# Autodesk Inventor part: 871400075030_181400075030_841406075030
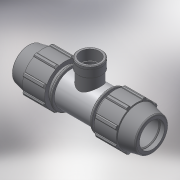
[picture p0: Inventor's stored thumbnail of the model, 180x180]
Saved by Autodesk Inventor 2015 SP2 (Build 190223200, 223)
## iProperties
Created: 2017-02
Part Number: 871400075030_181400075030_841406075030
Material: Generic
Description: PLASSON TEE WITH THREADED FEMALE OFFTAKE 75-3"-75
Document SubType Name: Modeling
Designer: KIM
Mass: 92.6774 g
Surface Area: 199.44 cm^2
Volume: 66.1981 cm^3
Density: 1 g/cm^3
Appearance: Default
Author: KIM
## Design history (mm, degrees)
derived "87140.ipt"
feature "Solid1::87140.ipt"
feature "Solid2::87140.ipt"
tag "TaggingFeature1"
body "Solid1"
other parameters: "d2" = 75, "d4" = 15.41667, "d5" = 44.4, "d7" = 132, "d11" = 6.16667, "d13" = 120 deg, "d14" = 97.5, "d15" = 12 deg, "d16" = 114.84, "d18" = 3.75, "d19" = 35 deg, "d20" = 17.5 deg, "d21" = 122.76, "d23" = 0, "d25" = 360 deg, "d27" = 2.64, "d33" = 1.5, "d42" = 66.6, "d43" = 3.96, "d46" = 2.25, "d68" = 11.1, "d76" = 84.926, "d80" = 2.54778, "d91" = 99, "d93" = 137, "d95" = 67.5, "d112" = 36, "d115" = 106.1575, "d116" = 135 deg, "d117" = 97.6649, "d119" = 67.5, "d121" = 0, "d122" = 67.5, "d124" = 0, "d128" = 0, "d129" = 7.5, "d130" = 10.8, "d131" = 0.3, "d132" = 0.3, "d133" = 106.1575, "d_" = 75, "E_" = 132, "l_" = 137, "l_2" = 36, "Rp_" = 84.926
